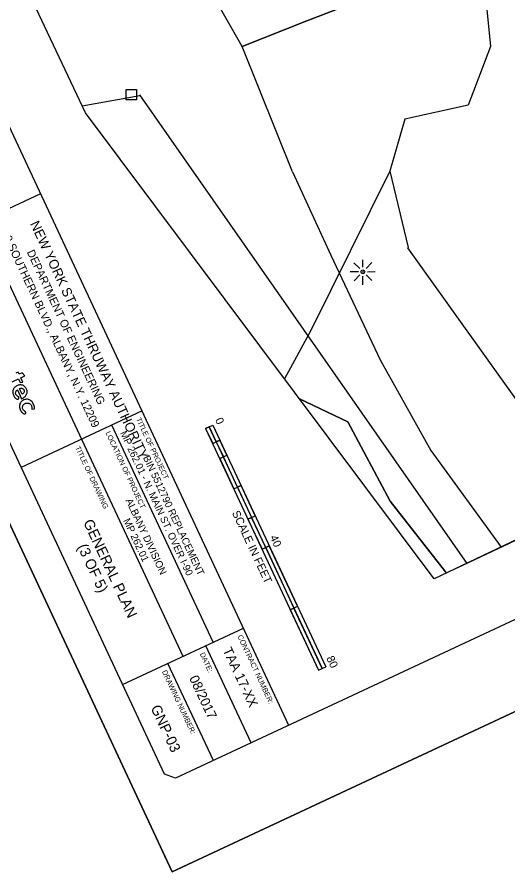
# Model space of a CAD drawing. Extents: x 1040567 to 1041254, y 1126791 to 1127594.
# Drawn here: x 1040808.5 to 1040955.8, y 1126791.3 to 1127047.7 of the extents above; entities that cross this region are included whole.
import ezdxf

# ---------------------------------------------------------------- set-up
doc = ezdxf.new("R2010")
doc.units = 0
for name, color, linetype in [('clip boundary', 7, 'Continuous'), ('G-ANNO-LOGO', 7, 'Continuous'), ('LABL', 7, 'Continuous'), ('LAM', 7, 'Continuous'), ('LAWA', 7, 'Continuous'), ('LELB', 7, 'Continuous'), ('LFNC', 7, 'Continuous'), ('LTC', 7, 'Continuous'), ('MHB', 7, 'Continuous'), ('MPM', 7, 'Continuous'), ('NML_P', 7, 'Continuous'), ('NSB_P', 7, 'Continuous'), ('O_Details_Text Title and Subtitle Proposed_P_T', 7, 'Continuous'), ('SHEET_BORDER', 7, 'Continuous'), ('SHEET_BORDER_CUT', 7, 'Continuous'), ('SHEET_BORDER_TEXT', 7, 'Continuous')]:
    doc.layers.add(name, color=color, linetype=linetype)

msp = doc.modelspace()

# ---------------------------------------------------------------- linework, layer by layer
at = {"layer": 'clip boundary'}
for points in [[(1040965.89, 1127593.65), (1041253.68, 1126977.55), (1040855.03, 1126791.33), (1040567.24, 1127407.43)], [(1040984.84, 1127512.73), (1041214.88, 1127013.05), (1040933.62, 1126879.17), (1040829.04, 1127018.95), (1040710.75, 1127268.88), (1040738.34, 1127281.77), (1040695.57, 1127374.92)]]:
    msp.add_lwpolyline(points, close=True, dxfattribs=at)
at = {"layer": 'G-ANNO-LOGO'}
for p, q in [((1040808.83, 1126941.23), (1040808.1, 1126940.89)), ((1040809.14, 1126940.56), (1040808.83, 1126941.23)), ((1040810.02, 1126940.97), (1040809.14, 1126940.56)), ((1040809.63, 1126939.51), (1040810.8, 1126940.05)), ((1040810.27, 1126938.14), (1040809.63, 1126939.51)), ((1040810.8, 1126940.05), (1040810.02, 1126940.97)), ((1040807.04, 1126938.32), (1040808.9, 1126939.17)), ((1040808.9, 1126939.17), (1040809.42, 1126938.06)), ((1040809.42, 1126938.06), (1040810.27, 1126938.14)), ((1040808.62, 1126935.91), (1040809.87, 1126933.24)), ((1040810.01, 1126934.61), (1040809.26, 1126936.21)), ((1040812.91, 1126930.12), (1040813.71, 1126930.21))]:
    msp.add_line(p, q, dxfattribs=at)
for points in [[(1040809.87, 1126933.24), (1040809.97, 1126933.28), (1040810.23, 1126933.39), (1040810.62, 1126933.63), (1040811.04, 1126933.95), (1040811.29, 1126934.34), (1040811.48, 1126934.74), (1040811.55, 1126935.16), (1040811.52, 1126935.63), (1040811.34, 1126936.1), (1040811.12, 1126936.54), (1040810.79, 1126936.9), (1040810.42, 1126937.17), (1040809.97, 1126937.34), (1040809.51, 1126937.39), (1040809.05, 1126937.32), (1040808.63, 1126937.18), (1040808.19, 1126936.98), (1040807.83, 1126936.69), (1040807.51, 1126936.35), (1040807.28, 1126935.94), (1040807.19, 1126935.45), (1040807.18, 1126934.88), (1040807.4, 1126934.33), (1040807.63, 1126933.84), (1040807.92, 1126933.46), (1040808.23, 1126933.21), (1040808.55, 1126933.07), (1040808.81, 1126933.09), (1040808.98, 1126933.21), (1040809.08, 1126933.37), (1040809.05, 1126933.53), (1040809.01, 1126933.68), (1040808.88, 1126933.82), (1040808.67, 1126933.96), (1040808.43, 1126934.12), (1040808.24, 1126934.36), (1040808.11, 1126934.61), (1040808.06, 1126934.89), (1040808.11, 1126935.16), (1040808.18, 1126935.44), (1040808.35, 1126935.67), (1040808.49, 1126935.83), (1040808.59, 1126935.89), (1040808.62, 1126935.91)], [(1040809.26, 1126936.21), (1040809.3, 1126936.23), (1040809.38, 1126936.27), (1040809.54, 1126936.33), (1040809.77, 1126936.37), (1040810.04, 1126936.35), (1040810.3, 1126936.23), (1040810.52, 1126936.01), (1040810.66, 1126935.73), (1040810.7, 1126935.42), (1040810.66, 1126935.13), (1040810.47, 1126934.9), (1040810.25, 1126934.73), (1040810.09, 1126934.65), (1040810.01, 1126934.61)], [(1040813.71, 1126930.21), (1040813.72, 1126930.32), (1040813.74, 1126930.6), (1040813.65, 1126931.07), (1040813.45, 1126931.63), (1040813.12, 1126932.17), (1040812.7, 1126932.63), (1040812.19, 1126932.93), (1040811.63, 1126933.07), (1040811.07, 1126933.05), (1040810.51, 1126932.87), (1040810, 1126932.59), (1040809.61, 1126932.18), (1040809.37, 1126931.75), (1040809.23, 1126931.22), (1040809.23, 1126930.6), (1040809.41, 1126929.96), (1040809.71, 1126929.43), (1040810.04, 1126929.03), (1040810.37, 1126928.75), (1040810.7, 1126928.62), (1040810.93, 1126928.71), (1040811.08, 1126928.8), (1040811.12, 1126928.96), (1040811.14, 1126929.1), (1040811.09, 1126929.22), (1040810.99, 1126929.38), (1040810.79, 1126929.46), (1040810.6, 1126929.63), (1040810.4, 1126929.8), (1040810.23, 1126930.09), (1040810.11, 1126930.43), (1040810.14, 1126930.81), (1040810.26, 1126931.15), (1040810.45, 1126931.46), (1040810.75, 1126931.67), (1040811.06, 1126931.87), (1040811.42, 1126931.93), (1040811.77, 1126931.94), (1040812.09, 1126931.87), (1040812.38, 1126931.7), (1040812.62, 1126931.47), (1040812.8, 1126931.16), (1040812.92, 1126930.82), (1040812.97, 1126930.45), (1040812.93, 1126930.23), (1040812.91, 1126930.12)]]:
    msp.add_open_spline(points, degree=3, dxfattribs=at)
at = {"layer": 'LABL'}
for points in [[(1040931.4, 1127059.5), (1040948.17, 1127063.13), (1040950.55, 1127038.81), (1040943.81, 1127021.3), (1040924.85, 1127017.05), (1040920.29, 1127001.5), (1040896.66, 1126953.7), (1040888.74, 1126939.15)], [(1040876.08, 1127038.85), (1040895.44, 1127046.57), (1040906.11, 1127050.61), (1040931.4, 1127059.5)]]:
    msp.add_lwpolyline(points, dxfattribs=at)
at = {"layer": 'LAM'}
msp.add_lwpolyline([(1040937.28, 1126880.91), (1040937.02, 1126881.29), (1040920.43, 1126902.48), (1040907.75, 1126926.25), (1040893.22, 1126933.16)], dxfattribs=at)
at = {"layer": 'LAWA'}
msp.add_lwpolyline([(1040893.22, 1126933.16), (1040907.75, 1126926.25), (1040920.43, 1126902.48), (1040937.02, 1126881.29), (1040937.28, 1126880.91)], dxfattribs=at)
at = {"layer": 'LELB'}
for points in [[(1040876.08, 1127038.85), (1040864.85, 1127058.55), (1040864.5, 1127061.61), (1040864.54, 1127064.69), (1040864.98, 1127067.74), (1040865.81, 1127070.71), (1040867.02, 1127073.54), (1040868.59, 1127076.2), (1040870.48, 1127078.62), (1040872.68, 1127080.79), (1040875.13, 1127082.65), (1040875.19, 1127082.68), (1040897.48, 1127088.21), (1040924.51, 1127096.31)], [(1040891.09, 1127001.24), (1040876.08, 1127038.85)], [(1040891.09, 1127001.24), (1040902.64, 1126976.24), (1040917.45, 1126944.9), (1040932.66, 1126917.69), (1040953.75, 1126888.75)], [(1040920.29, 1127001.5), (1040925.79, 1126978.59), (1040925.64, 1126978.49), (1040961.5, 1126928.27), (1040976.45, 1126899.56)]]:
    msp.add_lwpolyline(points, dxfattribs=at)
at = {"layer": 'LFNC'}
msp.add_lwpolyline([(1040985.41, 1127080.2), (1040973.96, 1127076.14), (1040954.71, 1127068.57), (1040931.4, 1127059.5), (1040906.11, 1127050.61), (1040895.44, 1127046.57), (1040876.08, 1127038.85)], dxfattribs=at)
at = {"layer": 'LTC'}
for points in [[(1040911.31, 1126972.28), (1040909.58, 1126974)], [(1040912.25, 1126972.66), (1040912.25, 1126974.89)], [(1040913.23, 1126972.28), (1040914.95, 1126974.03)], [(1040910.9, 1126971.27), (1040908.39, 1126971.27)], [(1040911.31, 1126970.33), (1040909.59, 1126968.58)], [(1040912.26, 1126967.33), (1040912.22, 1126969.98)], [(1040913.26, 1126970.37), (1040914.98, 1126968.64)], [(1040913.62, 1126971.31), (1040915.95, 1126971.34)]]:
    msp.add_lwpolyline(points, dxfattribs=at)
for radius in [0.573, 0.0699]:
    msp.add_circle((1040912.24, 1126971.26), radius, dxfattribs=at)
at = {"layer": 'MHB'}
for points in [[(1040828.03, 1127021.08), (1040845.35, 1127024.18)], [(1040845.21, 1127024.37), (1040943.43, 1126883.84)]]:
    msp.add_lwpolyline(points, dxfattribs=at)
at = {"layer": 'MPM'}
for p, q in [((1040841.2, 1127022.86), (1040841.2, 1127025.92)), ((1040841.2, 1127025.92), (1040844.35, 1127025.92)), ((1040844.35, 1127025.92), (1040844.35, 1127022.86)), ((1040844.35, 1127022.86), (1040841.2, 1127022.86))]:
    msp.add_line(p, q, dxfattribs=at)
at = {"layer": 'NML_P'}
msp.add_line((1040940.57, 1126882.48), (1041214.88, 1127013.05), dxfattribs=at)
at = {"layer": 'NSB_P'}
for p, q in [((1040865.07, 1126924.32), (1040867.25, 1126925.33)), ((1040866.16, 1126924.83), (1040865.07, 1126924.32)), ((1040865.07, 1126924.32), (1040898.93, 1126851.84)), ((1040865.07, 1126924.32), (1040867.19, 1126919.79)), ((1040866.16, 1126924.83), (1040900.02, 1126852.34)), ((1040868.28, 1126920.3), (1040866.16, 1126924.83)), ((1040867.25, 1126925.33), (1040901.11, 1126852.85)), ((1040867.19, 1126919.79), (1040869.37, 1126920.8)), ((1040867.19, 1126919.79), (1040868.28, 1126920.3)), ((1040869.37, 1126920.8), (1040868.28, 1126920.3)), ((1040868.28, 1126920.3), (1040870.39, 1126915.77)), ((1040871.48, 1126916.27), (1040869.37, 1126920.8)), ((1040869.31, 1126915.26), (1040871.48, 1126916.27)), ((1040870.39, 1126915.77), (1040871.48, 1126916.27)), ((1040870.39, 1126915.77), (1040869.31, 1126915.26)), ((1040869.31, 1126915.26), (1040873.54, 1126906.2)), ((1040874.63, 1126906.71), (1040870.39, 1126915.77)), ((1040873.54, 1126906.2), (1040875.71, 1126907.21)), ((1040873.54, 1126906.2), (1040874.63, 1126906.71)), ((1040875.71, 1126907.21), (1040874.63, 1126906.71)), ((1040874.63, 1126906.71), (1040878.86, 1126897.65)), ((1040879.95, 1126898.15), (1040875.71, 1126907.21)), ((1040877.77, 1126897.14), (1040879.95, 1126898.15)), ((1040878.86, 1126897.65), (1040877.77, 1126897.14)), ((1040877.77, 1126897.14), (1040882, 1126888.08)), ((1040878.86, 1126897.65), (1040879.95, 1126898.15)), ((1040883.09, 1126888.59), (1040878.86, 1126897.65)), ((1040882, 1126888.08), (1040884.18, 1126889.09)), ((1040882, 1126888.08), (1040883.09, 1126888.59)), ((1040884.18, 1126889.09), (1040883.09, 1126888.59)), ((1040883.09, 1126888.59), (1040891.56, 1126870.46)), ((1040892.64, 1126870.97), (1040884.18, 1126889.09)), ((1040890.47, 1126869.96), (1040892.64, 1126870.97)), ((1040891.56, 1126870.46), (1040890.47, 1126869.96)), ((1040891.56, 1126870.46), (1040892.64, 1126870.97)), ((1040900.02, 1126852.34), (1040891.56, 1126870.46)), ((1040890.47, 1126869.96), (1040898.93, 1126851.84)), ((1040898.93, 1126851.84), (1040901.11, 1126852.85)), ((1040898.93, 1126851.84), (1040900.02, 1126852.34))]:
    msp.add_line(p, q, dxfattribs=at)
at = {"layer": 'SHEET_BORDER'}
for p, q in [((1040890.04, 1126835.28), (1040747.91, 1127139.53)), ((1040815.57, 1126994.68), (1040779.33, 1126977.75)), ((1040858.29, 1126855.97), (1040797.45, 1126986.22)), ((1040845.99, 1126929.56), (1040809.75, 1126912.63)), ((1040867.35, 1126860.21), (1040836.93, 1126925.33)), ((1040840.17, 1126847.51), (1040876.41, 1126864.44)), ((1040878.71, 1126829.99), (1040865.09, 1126859.15)), ((1040867.39, 1126824.7), (1040853.76, 1126853.86))]:
    msp.add_line(p, q, dxfattribs=at)
msp.add_lwpolyline([(1040856.06, 1126819.41), (1040852.74, 1126820.61), (1040588.22, 1127386.88), (1040589.43, 1127390.2), (1040964.86, 1127565.58), (1040968.18, 1127564.37), (1041232.7, 1126998.11), (1041231.49, 1126994.78)], close=True, dxfattribs=at)
at = {"layer": 'SHEET_BORDER_CUT'}
msp.add_lwpolyline([(1040567.24, 1127407.43), (1040855.03, 1126791.33), (1041253.68, 1126977.55), (1040965.89, 1127593.65)], close=True, dxfattribs=at)
msp.add_lwpolyline([(1040861.44, 1126794.33), (1040855.03, 1126791.33), (1040852.04, 1126797.74)], dxfattribs=at)
at = {"layer": 'SHEET_BORDER_TEXT'}
msp.add_line((1040855.03, 1126791.33), (1040855.03, 1126791.33), dxfattribs=at)

# ---------------------------------------------------------------- texts
at = {"layer": 'NSB_P'}
for s, p in [('0', (1040867.85, 1126926.88)), ('SCALE IN FEET', (1040872.91, 1126899.03)), ('40', (1040884.3, 1126891.67)), ('80', (1040901.23, 1126855.43))]:
    msp.add_text(s, height=2.4, rotation=295.0387, dxfattribs=at).set_placement(p)
at = {"layer": 'O_Details_Text Title and Subtitle Proposed_P_T'}
for s, height, p in [('GENERAL PLAN', 3.1248, (1040828.29, 1126896.18)), ('(3 OF 5)', 3.125, (1040826.55, 1126888.84)), ('GNP-03', 3.125, (1040848.5, 1126840.53))]:
    msp.add_text(s, height=height, rotation=295.0387, dxfattribs=at).set_placement(p)
at = {"layer": 'SHEET_BORDER'}
for s, height, p in [('200 SOUTHERN BLVD., ALBANY, N.Y. 12209', 2.4, (1040802.98, 1126984.74)), ('NEW YORK STATE THRUWAY AUTHORITY', 2.88, (1040812.33, 1126985.72)), ('DEPARTMENT OF ENGINEERING', 2.4, (1040811.38, 1126977.21)), ('TITLE OF PROJECT', 1.5625, (1040844.16, 1126927.11)), ('LOCATION OF PROJECT', 1.5625, (1040834.99, 1126923.02)), ('TITLE OF DRAWING', 1.5625, (1040825.9, 1126918.58)), ('CONTRACT NUMBER:', 1.5625, (1040874.58, 1126861.99)), ('DATE:', 1.562, (1040863.26, 1126856.7)), ('DRAWING NUMBER:', 1.5625, (1040851.93, 1126851.41))]:
    msp.add_text(s, height=height, rotation=295.0387, dxfattribs=at).set_placement(p)
at = {"layer": 'SHEET_BORDER_TEXT'}
for s, height, p in [('MP 262.01 - N. MAIN ST. OVER I-90', 2.16, (1040839.35, 1126922.95)), ('BIN 5512790 REPLACEMENT', 2.16, (1040846.22, 1126915.6)), ('ALBANY DIVISION', 2.16, (1040841.02, 1126902.73)), ('MP 262.01', 2.16, (1040840.31, 1126896.72)), ('TAA 17-XX', 2.88, (1040870.13, 1126857.86)), ('08/2017', 2.88, (1040860.07, 1126849.45))]:
    msp.add_text(s, height=height, rotation=295.0387, dxfattribs=at).set_placement(p)

doc.saveas('drawing.dxf')
